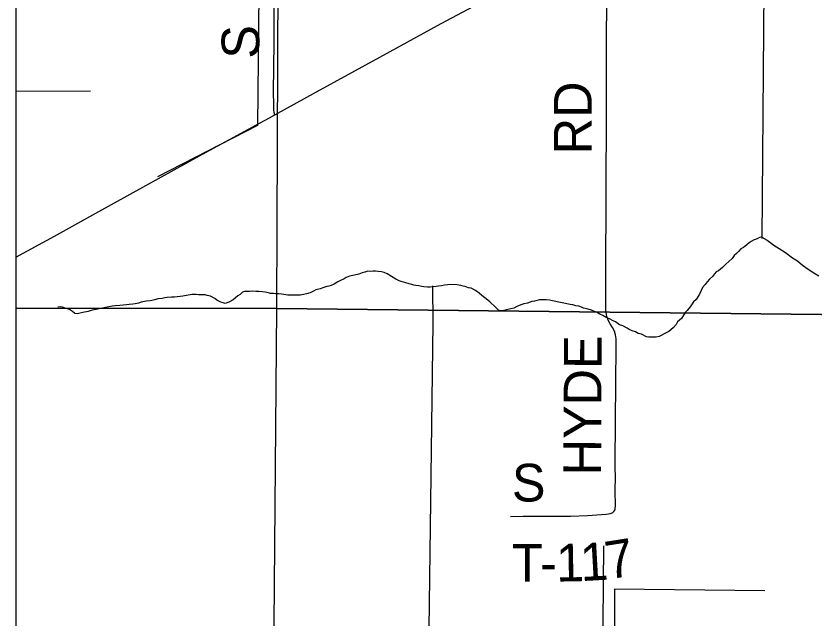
# Model space of a CAD drawing. Extents: x 0 to 34, y 0 to 22.
# Drawn here: x 2.1 to 2.701, y 17.217 to 17.671 of the extents above; entities that cross this region are included whole.
import ezdxf

# ---------------------------------------------------------------- set-up
doc = ezdxf.new("R2010")
doc.units = 0
for name, color, linetype in [('GM_X_Corporation', 7, 'Continuous'), ('GM_X_Minor_River', 7, 'Continuous'), ('GM_X_State_Route', 7, 'Continuous'), ('GM_X_Township_Road', 7, 'Continuous'), ('GM_X_Township_Road_Text', 7, 'Continuous')]:
    doc.layers.add(name, color=color, linetype=linetype)

msp = doc.modelspace()

# ---------------------------------------------------------------- linework, layer by layer
at = {"layer": 'GM_X_Corporation'}
for points in [[(2.1, 19.23555), (2.1, 16.59135)], [(3.00478, 18.43707), (2.97992, 18.42919), (2.92938, 18.42252), (2.66141, 18.41843), (2.5349, 18.41088), (2.48912, 18.40358), (2.36749, 18.37012), (2.29892, 18.34983), (2.2944, 18.34848), (2.29017, 18.34722), (2.28004, 18.34423), (2.20498, 18.31695), (2.13026, 18.28436), (2.1, 18.27405), (2.1, 16.59135)]]:
    msp.add_lwpolyline(points, dxfattribs=at)
for points in [[(2.1, 17.94805), (2.1, 17.45044), (2.29652, 17.45028), (2.29863, 17.94779)], [(2.79974, 17.94803), (2.79816, 17.44485), (2.29652, 17.45028), (2.29863, 17.94779)], [(2.1, 17.45044), (2.1, 16.94501), (2.2924, 16.94427), (2.29652, 17.45028)], [(2.79816, 17.44485), (2.79596, 16.94452), (2.2924, 16.94427), (2.29652, 17.45028)]]:
    msp.add_lwpolyline(points, close=True, dxfattribs=at)
at = {"layer": 'GM_X_Minor_River'}
msp.add_line((2.1, 17.61406), (2.15629, 17.61441), dxfattribs=at)
for points in [[(2.28462, 17.83731), (2.2819, 17.58821), (2.20674, 17.54965)], [(2.66435, 17.78557), (2.66201, 17.50315)], [(2.66202, 17.50429), (2.6603, 17.50371), (2.65859, 17.50294), (2.65632, 17.50198), (2.65405, 17.50083), (2.65253, 17.49968), (2.65083, 17.49834), (2.64818, 17.49624), (2.64629, 17.49528), (2.6444, 17.49337), (2.64289, 17.49165), (2.64119, 17.49032), (2.63968, 17.48803), (2.63723, 17.48573), (2.63496, 17.48382), (2.63232, 17.48115), (2.62929, 17.47867), (2.62759, 17.4779), (2.62646, 17.47637), (2.62476, 17.47446), (2.62249, 17.47236), (2.62079, 17.47045), (2.61928, 17.46836), (2.6174, 17.46607), (2.61627, 17.46397), (2.61495, 17.46111), (2.61251, 17.45711), (2.61043, 17.45539), (2.60798, 17.45158), (2.60572, 17.44872), (2.6042, 17.44719), (2.60138, 17.4428), (2.59855, 17.44013), (2.59742, 17.43822), (2.59515, 17.43574), (2.59194, 17.43307), (2.59005, 17.43192), (2.58474, 17.42923), (2.58247, 17.42865), (2.57696, 17.42863), (2.57525, 17.429), (2.57126, 17.43088), (2.56879, 17.43144), (2.56688, 17.43276), (2.56441, 17.43351), (2.56213, 17.43445), (2.5606, 17.43558), (2.55718, 17.43727), (2.5549, 17.43802), (2.55166, 17.44029), (2.54995, 17.44104), (2.54728, 17.44255), (2.54481, 17.44349), (2.54214, 17.445), (2.54005, 17.44613), (2.53738, 17.44763), (2.53586, 17.44801), (2.53358, 17.44914), (2.53111, 17.4497), (2.52769, 17.45063), (2.52616, 17.45119), (2.52407, 17.45194), (2.52198, 17.45231), (2.5197, 17.45306), (2.51761, 17.45343), (2.50431, 17.45603), (2.50203, 17.45659), (2.49956, 17.45677), (2.49728, 17.45676), (2.49462, 17.45675), (2.49064, 17.45578), (2.48874, 17.45558), (2.48552, 17.45442), (2.48268, 17.45384), (2.48116, 17.45326), (2.47927, 17.45249), (2.47737, 17.45191), (2.4751, 17.45057), (2.47055, 17.4496), (2.46771, 17.44883), (2.46543, 17.44862), (2.46372, 17.449), (2.46143, 17.45127), (2.45704, 17.45543), (2.45552, 17.45656), (2.45342, 17.45845), (2.45113, 17.46015), (2.44904, 17.46185), (2.44618, 17.46393), (2.44313, 17.46562), (2.44104, 17.46599), (2.43857, 17.46693), (2.43705, 17.46712), (2.43515, 17.46768), (2.43249, 17.46804), (2.42774, 17.4684), (2.42527, 17.4682), (2.423, 17.468), (2.42072, 17.46742), (2.41845, 17.46722), (2.41655, 17.46683)], [(2.66201, 17.5041), (2.666, 17.50184), (2.67095, 17.49806), (2.67514, 17.49561), (2.67991, 17.49259), (2.68505, 17.48862), (2.68886, 17.48617), (2.69267, 17.48296), (2.69705, 17.47994), (2.70125, 17.47711), (2.70505, 17.47484)], [(2.41655, 17.46683), (2.41408, 17.46663), (2.412, 17.46643), (2.4101, 17.46642), (2.40744, 17.4666), (2.40592, 17.46678), (2.40345, 17.46734), (2.40136, 17.46771), (2.39984, 17.46789), (2.39832, 17.46845), (2.39623, 17.46901), (2.393, 17.46995), (2.39109, 17.47051), (2.38881, 17.47126), (2.38634, 17.47239), (2.37967, 17.47635), (2.37739, 17.47748), (2.37549, 17.47785), (2.37283, 17.47822), (2.37093, 17.4784), (2.36922, 17.47839), (2.36695, 17.47819), (2.36524, 17.47837), (2.36296, 17.47779), (2.36088, 17.47721), (2.35841, 17.47625), (2.35519, 17.47547), (2.3514, 17.47469), (2.34875, 17.47373), (2.34723, 17.47258), (2.34401, 17.47105), (2.3425, 17.47028), (2.33966, 17.46856), (2.33739, 17.4676), (2.33587, 17.46721), (2.33435, 17.46701), (2.33208, 17.46605), (2.32924, 17.46509), (2.32601, 17.46431), (2.32412, 17.46335), (2.32166, 17.4622), (2.31882, 17.46124), (2.31673, 17.46085), (2.31407, 17.46026), (2.31123, 17.46025), (2.30895, 17.46043), (2.30496, 17.46041), (2.30173, 17.46097), (2.30021, 17.46115), (2.29812, 17.46133), (2.29566, 17.46132), (2.29414, 17.4615), (2.29186, 17.46168), (2.29034, 17.46205), (2.28787, 17.46261), (2.28578, 17.46279), (2.28312, 17.46316), (2.28065, 17.46315), (2.27799, 17.46332), (2.2759, 17.46312), (2.2723, 17.46311), (2.27059, 17.46253), (2.26889, 17.46081), (2.26719, 17.45985), (2.2636, 17.45679), (2.26038, 17.45507), (2.25773, 17.45411), (2.25601, 17.45467), (2.25449, 17.45504), (2.25297, 17.45579), (2.25145, 17.45655), (2.24973, 17.45787), (2.2465, 17.45956), (2.24403, 17.46012), (2.24251, 17.4605), (2.23966, 17.46067), (2.23757, 17.46066), (2.23586, 17.46084), (2.23282, 17.46083), (2.22979, 17.46025), (2.22581, 17.45966), (2.21936, 17.45887), (2.21708, 17.45886), (2.21404, 17.45865), (2.21214, 17.45826), (2.21006, 17.45787), (2.20683, 17.45748), (2.20475, 17.4569), (2.20115, 17.45612), (2.19811, 17.45573), (2.19432, 17.45495), (2.19223, 17.45437), (2.18977, 17.45379), (2.18806, 17.45359), (2.1854, 17.45338), (2.18332, 17.45299), (2.18066, 17.45279), (2.17819, 17.45259), (2.17478, 17.45238), (2.1725, 17.45199), (2.16871, 17.45141)], [(2.41389, 17.46739), (2.41403, 17.43945), (2.40749, 16.93959)], [(2.16871, 17.45141), (2.16056, 17.44947), (2.15752, 17.44907), (2.15449, 17.44811), (2.15051, 17.44733), (2.14615, 17.44617), (2.14443, 17.44654), (2.14272, 17.44805), (2.14043, 17.44956), (2.13891, 17.44993), (2.1372, 17.4505), (2.13511, 17.45125), (2.1334, 17.45162), (2.1315, 17.45142)], [(2.54284, 17.27129), (2.54196, 17.18406), (2.53325, 17.18136), (2.53467, 16.97896), (2.53511, 16.92974), (2.44419, 16.92855)], [(2.66432, 17.23747), (2.55098, 17.23864), (2.55071, 17.18163)]]:
    msp.add_lwpolyline(points, dxfattribs=at)
at = {"layer": 'GM_X_State_Route'}
msp.add_lwpolyline([(2.1, 17.48893), (2.12898, 17.50491), (2.16027, 17.52222), (2.18615, 17.53647), (2.24061, 17.56653), (2.28412, 17.59031), (2.29101, 17.59395), (2.29509, 17.59622), (2.32637, 17.61356), (2.37408, 17.63972), (2.42046, 17.66512), (2.45681, 17.68486), (2.46134, 17.68732), (2.47262, 17.6936), (2.50345, 17.71077), (2.53322, 17.72729), (2.54335, 17.73295), (2.59987, 17.76453), (2.62294, 17.77744), (2.66088, 17.79858), (2.68128, 17.80989), (2.73729, 17.84118)], dxfattribs=at)
at = {"layer": 'GM_X_Township_Road'}
for points in [[(2.29509, 17.59622), (2.29468, 17.59815), (2.29438, 17.60018), (2.29421, 17.60415), (2.29415, 17.61342), (2.29453, 17.65082), (2.29467, 17.6726), (2.29459, 17.68659), (2.29442, 17.69351), (2.29439, 17.69525)], [(2.47269, 17.29341), (2.48209, 17.29372), (2.49933, 17.29362), (2.51792, 17.2937), (2.53063, 17.29425), (2.54475, 17.2953), (2.54649, 17.29542), (2.54783, 17.29569), (2.5485, 17.29591), (2.54916, 17.29624), (2.54975, 17.29657), (2.55054, 17.29719), (2.55116, 17.29824), (2.55143, 17.29899), (2.55156, 17.29965), (2.55167, 17.30104), (2.55161, 17.31364), (2.55165, 17.32298), (2.55161, 17.33077), (2.55185, 17.36814), (2.55195, 17.39149), (2.55237, 17.4242), (2.55228, 17.42731), (2.55184, 17.43037), (2.55091, 17.43331), (2.54949, 17.43607), (2.54784, 17.43874), (2.54634, 17.44146), (2.54525, 17.44435), (2.54491, 17.44586), (2.54447, 17.44893), (2.54436, 17.45205), (2.5445, 17.45985), (2.54449, 17.48632), (2.54479, 17.5268), (2.54484, 17.55016), (2.54502, 17.58597), (2.54511, 17.64669), (2.5451, 17.66226), (2.54562, 17.69184)]]:
    msp.add_lwpolyline(points, dxfattribs=at)

# ---------------------------------------------------------------- texts
at = {"layer": 'GM_X_Township_Road_Text'}
for s, height, rotation, p in [('S', 0.02841, 90, (2.28337, 17.63862)), ('RD', 0.028409, 90, (2.53379, 17.56654)), ('HYDE', 0.028409, 89.75248, (2.54088, 17.32442)), ('S', 0.02841, 0.00001, (2.47371, 17.3048)), ('T', 0.02841, 0.02571, (2.47372, 17.24431)), ('1', 0.02841, 1.08686, (2.50721, 17.24438)), ('1', 0.02841, 3.13059, (2.52581, 17.24475)), ('7', 0.02841, 8.97828, (2.54642, 17.24604)), ('-', 0.02841, 0.2635, (2.49509, 17.24432))]:
    msp.add_text(s, height=height, rotation=rotation, dxfattribs=at).set_placement(p)

doc.saveas('drawing.dxf')
